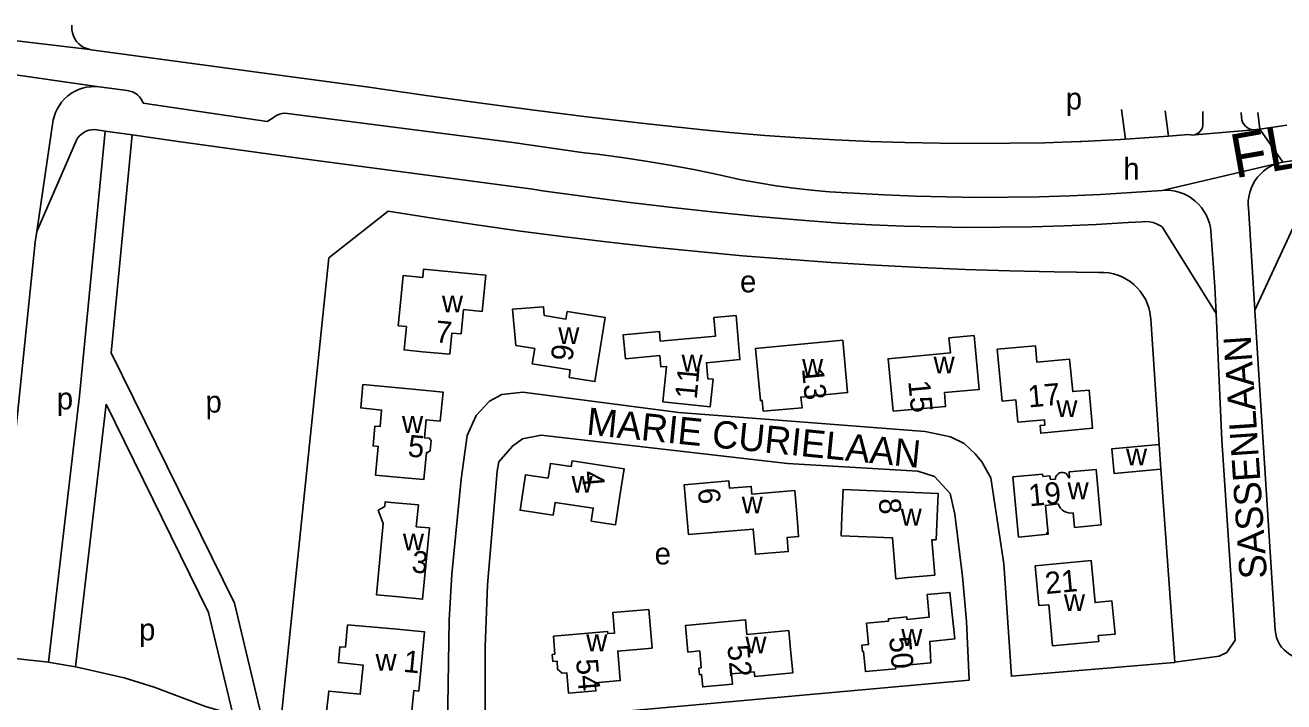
# Model space of a CAD drawing. Extents: x 161093 to 163177, y 379000 to 380904.
# Drawn here: x 162248.8 to 162479, y 380640.8 to 380764.5 of the extents above; entities that cross this region are included whole.
import ezdxf

# ---------------------------------------------------------------- set-up
doc = ezdxf.new("R2010")
doc.units = 0
for name, color, linetype in [('BLT_Basislijn', 7, 'Continuous'), ('BLT_Bebouwing', 7, 'Continuous'), ('BLT_Centroide', 7, 'Continuous'), ('BLT_Huisnummer', 7, 'Continuous'), ('BLT_Straatnaam', 7, 'Continuous'), ('BLT_Straatnaam_hoofdweg', 7, 'Continuous'), ('BLT_Vlakafsluiter', 7, 'Continuous')]:
    doc.layers.add(name, color=color, linetype=linetype)

msp = doc.modelspace()

# ---------------------------------------------------------------- linework, layer by layer
at = {"layer": 'BLT_Basislijn'}
for p, q in [((162262.39, 380753.23), (162267.46, 380752.57)), ((162449.31, 380749.09), (162450.04, 380743.7)), ((162457.32, 380748.88), (162457.95, 380744.25)), ((162464.21, 380748.71), (162464.22, 380746.59)), ((162471.22, 380748.53), (162471.26, 380747.62)), ((162474.25, 380748.54), (162474.64, 380745.52)), ((162261.55, 380745.42), (162263.47, 380745.15)), ((162263.47, 380745.15), (162268.42, 380744.44)), ((162268.42, 380744.44), (162264.57, 380704.6)), ((162268.42, 380744.44), (162276.36, 380743.32)), ((162457.95, 380744.25), (162461.6, 380744.54)), ((162474.64, 380745.52), (162479.59, 380746.21)), ((162258.22, 380743.49), (162250.94, 380726.78)), ((162481.21, 380739.85), (162478.83, 380739.49)), ((162472.53, 380731.15), (162473.7, 380712.42)), ((162481.88, 380730.02), (162473.7, 380712.42)), ((162456.75, 380727.66), (162466.64, 380711.77)), ((162473.7, 380712.42), (162474.2, 380704.45)), ((162466.64, 380711.77), (162467.69, 380688.62)), ((162477.45, 380653.84), (162474.2, 380704.45)), ((162263.64, 380695.17), (162258.02, 380647.15)), ((162253.09, 380647.99), (162254.08, 380647.85)), ((162254.08, 380647.85), (162258.02, 380647.15)), ((162458.95, 380647.95), (162459.11, 380647.98)), ((162258.02, 380647.15), (162258.88, 380647))]:
    msp.add_line(p, q, dxfattribs=at)
for points in [[(162257.39, 380764.52), (162257.36, 380764.24), (162257.39, 380763.67), (162257.49, 380763.1), (162257.67, 380762.55), (162257.93, 380762.04), (162258.25, 380761.56), (162258.64, 380761.14), (162259.08, 380760.77), (162259.57, 380760.47), (162260.1, 380760.23), (162260.65, 380760.08)], [(162260.65, 380760.08), (162260.88, 380760.03), (162290.3, 380756.08), (162311.69, 380753.21)], [(162262.39, 380753.23), (162261.61, 380753.29), (162260.84, 380753.27), (162260.07, 380753.17), (162259.31, 380752.99), (162258.58, 380752.74), (162257.87, 380752.41), (162257.21, 380752.01), (162256.58, 380751.55), (162256.01, 380751.02), (162255.5, 380750.44), (162255.05, 380749.8), (162254.66, 380749.13), (162254.4, 380748.54)], [(162267.46, 380752.57), (162267.97, 380752.48), (162268.46, 380752.32), (162268.93, 380752.08), (162269.35, 380751.78), (162269.73, 380751.42), (162270.04, 380751), (162270.28, 380750.54), (162270.39, 380750.24)], [(162311.69, 380753.21), (162321.76, 380751.72), (162331.83, 380750.3), (162341.92, 380748.97), (162352.02, 380747.72), (162362.12, 380746.55), (162372.24, 380745.45), (162377.73, 380744.89)], [(162294.19, 380747.56), (162293.08, 380746.91), (162270.39, 380750.24)], [(162253.94, 380747.21), (162250.94, 380726.78)], [(162254.4, 380748.54), (162253.94, 380747.21)], [(162296.81, 380748.35), (162296.32, 380748.4), (162295.83, 380748.37), (162295.36, 380748.26), (162294.9, 380748.07), (162294.49, 380747.81), (162294.19, 380747.56)], [(162296.81, 380748.35), (162337.62, 380743.14), (162351.06, 380741.19)], [(162464.22, 380746.59), (162464.21, 380746.19), (162464.13, 380745.8), (162463.97, 380745.44), (162463.74, 380745.11), (162463.45, 380744.84), (162463.11, 380744.63), (162462.74, 380744.49)], [(162471.26, 380747.62), (162471.33, 380747.18), (162471.48, 380746.78), (162471.7, 380746.4), (162471.98, 380746.07), (162472.32, 380745.79), (162472.7, 380745.59), (162473.12, 380745.45), (162473.55, 380745.4)], [(162263.47, 380745.15), (162258.79, 380696.74), (162253.09, 380647.99)], [(162261.55, 380745.42), (162261.02, 380745.41), (162260.5, 380745.32), (162260, 380745.16), (162259.54, 380744.92), (162259.11, 380744.61), (162258.73, 380744.25), (162258.41, 380743.83), (162258.22, 380743.49)], [(162377.73, 380744.89), (162384.11, 380744.37), (162390.5, 380743.92), (162396.9, 380743.55), (162403.3, 380743.27), (162409.7, 380743.06), (162416.1, 380742.93), (162422.51, 380742.89), (162428.91, 380742.92), (162435.32, 380743.03), (162441.72, 380743.23), (162442.1, 380743.24)], [(162450.04, 380743.7), (162456.17, 380744.11), (162457.95, 380744.25)], [(162462.74, 380744.49), (162462.34, 380744.43), (162461.95, 380744.45), (162461.6, 380744.54)], [(162473.55, 380745.4), (162474.01, 380745.43), (162474.64, 380745.52)], [(162341.7, 380734.51), (162298.88, 380740.17), (162276.36, 380743.32)], [(162442.1, 380743.24), (162449.14, 380743.64), (162450.04, 380743.7)], [(162375.44, 380737.2), (162371.09, 380738.1), (162366.71, 380738.91), (162362.33, 380739.66), (162357.93, 380740.32), (162353.52, 380740.9), (162351.06, 380741.19)], [(162478.83, 380739.49), (162478.06, 380739.3), (162477.32, 380739.04), (162476.61, 380738.71), (162475.93, 380738.3), (162475.3, 380737.83), (162474.72, 380737.3), (162474.2, 380736.71), (162473.74, 380736.07), (162473.34, 380735.39), (162473.02, 380734.67), (162472.77, 380733.92), (162472.6, 380733.15), (162472.51, 380732.37), (162472.5, 380731.58), (162472.53, 380731.15)], [(162399.17, 380733.86), (162395.92, 380734.06), (162392.66, 380734.34), (162389.42, 380734.7), (162386.19, 380735.14), (162382.97, 380735.66), (162379.76, 380736.26), (162376.57, 380736.94), (162375.44, 380737.2)], [(162397.78, 380728.29), (162389.99, 380728.91), (162382.21, 380729.6), (162374.43, 380730.37), (162366.67, 380731.22), (162358.91, 380732.15), (162351.16, 380733.17), (162343.43, 380734.25), (162341.7, 380734.51)], [(162456.77, 380734.3), (162451.14, 380733.89), (162445.51, 380733.55), (162439.87, 380733.3), (162434.22, 380733.13), (162428.58, 380733.04), (162422.93, 380733.03), (162417.29, 380733.1), (162411.65, 380733.25), (162406.01, 380733.48), (162400.37, 380733.78), (162399.17, 380733.86)], [(162456.77, 380734.3), (162457.58, 380734.32), (162458.39, 380734.27), (162459.2, 380734.14), (162459.98, 380733.93), (162460.74, 380733.65), (162461.47, 380733.29), (162462.16, 380732.86), (162462.8, 380732.36), (162463.39, 380731.81), (162463.93, 380731.2), (162464.4, 380730.53), (162464.81, 380729.83), (162465.14, 380729.09), (162465.4, 380728.32), (162465.58, 380727.53), (162465.67, 380726.88)], [(162295.46, 380636.01), (162304.37, 380721.94), (162315.24, 380730.53)], [(162315.24, 380730.53), (162323.3, 380729.23), (162331.37, 380728.01), (162339.45, 380726.87), (162347.54, 380725.81), (162355.64, 380724.83), (162363.75, 380723.93), (162371.87, 380723.11), (162379.99, 380722.36), (162388.12, 380721.7), (162396.26, 380721.12), (162404.41, 380720.61), (162412.56, 380720.19), (162420.71, 380719.85), (162428.86, 380719.59), (162437.02, 380719.4), (162445.18, 380719.3), (162445.33, 380719.3)], [(162397.78, 380728.29), (162403.64, 380727.99), (162409.5, 380727.76), (162415.37, 380727.61), (162421.23, 380727.54), (162427.1, 380727.55), (162432.97, 380727.65), (162438.83, 380727.82), (162444.69, 380728.07), (162450.55, 380728.4), (162453.12, 380728.57)], [(162453.12, 380728.57), (162453.79, 380728.6), (162454.46, 380728.54), (162455.11, 380728.4), (162455.75, 380728.19), (162456.36, 380727.9), (162456.75, 380727.66)], [(162250.94, 380726.78), (162250.65, 380724.81), (162242.85, 380649.38)], [(162465.67, 380726.88), (162466.42, 380716.69), (162466.64, 380711.77)], [(162445.33, 380719.3), (162446.18, 380719.29), (162447.02, 380719.2), (162447.86, 380719.03), (162448.67, 380718.79), (162449.46, 380718.47), (162450.21, 380718.07), (162450.93, 380717.61), (162451.6, 380717.08), (162452.21, 380716.5), (162452.77, 380715.85), (162453.26, 380715.16), (162453.69, 380714.43), (162454.05, 380713.65), (162454.33, 380712.85), (162454.53, 380712.02), (162454.66, 380711.18), (162454.69, 380710.76)], [(162454.69, 380710.76), (162456.2, 380687.82)], [(162264.57, 380704.6), (162287.12, 380658.77), (162292.33, 380636.79)], [(162458.95, 380647.95), (162429.2, 380645.44), (162427.8, 380666.02), (162425.43, 380681.74), (162423.8, 380684.63), (162422.56, 380686.13), (162420.55, 380688.02), (162418.06, 380689.25), (162413.44, 380690.18), (162368.4, 380693.69), (162339.82, 380697.42), (162336.03, 380696.95), (162333.77, 380695.77), (162331.31, 380693.12), (162329.69, 380689.49), (162328.59, 380681.48), (162326.85, 380664.09), (162326.39, 380655.74), (162326.05, 380636.17), (162308.65, 380634.63), (162305.5, 380634.73), (162296.83, 380635.69), (162295.46, 380636.01)], [(162263.64, 380695.17), (162282.39, 380657.07), (162286.79, 380638.47)], [(162420.27, 380663.65), (162420.98, 380655.53), (162421.46, 380644.73), (162332.97, 380636.71), (162332.97, 380650.75), (162333.38, 380662.14), (162335.17, 380682.97), (162335.46, 380684.68), (162337.94, 380687.54), (162339.78, 380688.85), (162343.17, 380689.54), (162388.27, 380684.36), (162412.11, 380682.92), (162415.13, 380681.97), (162417.98, 380678.84), (162418.87, 380675.08), (162420.27, 380663.65)], [(162459.11, 380647.98), (162467.2, 380649.13), (162468.58, 380649.78), (162470.11, 380652.01), (162467.69, 380688.62)], [(162456.52, 380683.33), (162459.11, 380647.98)], [(162477.45, 380653.84), (162477.53, 380653.18), (162477.69, 380652.53), (162477.92, 380651.9), (162478.23, 380651.31), (162478.61, 380650.76), (162479.05, 380650.25), (162479.54, 380649.81), (162480.09, 380649.42), (162480.68, 380649.11), (162481.3, 380648.86), (162481.87, 380648.71)], [(162242.85, 380649.38), (162243.05, 380649.1), (162253.09, 380647.99)], [(162286.26, 380638.64), (162281.79, 380639.92), (162272.42, 380643.46), (162266.95, 380645.14), (162258.88, 380647)]]:
    msp.add_lwpolyline(points, dxfattribs=at)
at = {"layer": 'BLT_Bebouwing'}
for p, q in [((162456.52, 380683.33), (162456.2, 380687.82)), ((162439.7, 380681.74), (162439.82, 380681.75))]:
    msp.add_line(p, q, dxfattribs=at)
for points in [[(162321.51, 380704.8), (162326.48, 380704.32), (162326.87, 380708.21), (162328.56, 380708.04), (162329, 380712.49), (162332.39, 380712.15), (162333.05, 380718.78), (162321.67, 380719.87), (162321.53, 380718.38), (162317.95, 380718.72), (162317.47, 380713.74), (162317.06, 380709.54), (162318.56, 380709.4), (162318.14, 380705.12), (162321.51, 380704.8)], [(162338.55, 380705.94), (162337.97, 380712.6), (162343.65, 380713.03), (162343.77, 380711.4)], [(162343.77, 380711.4), (162347.74, 380710.76), (162347.96, 380712.15), (162354.91, 380711.04), (162353.04, 380699.34), (162348.33, 380700.09), (162348.52, 380701.46), (162341.57, 380702.59)], [(162364.98, 380706.71), (162375.06, 380707.64), (162374.75, 380711.03), (162378.83, 380711.41), (162379.55, 380703.36), (162373.42, 380702.77), (162373.7, 380699.86), (162374.66, 380699.75), (162374.1, 380694.69), (162365.43, 380695.65)], [(162364.98, 380706.71), (162364.81, 380708.51), (162358.2, 380707.9), (162358.61, 380703.51), (162364.9, 380704.1)], [(162407.56, 380693.89), (162417.16, 380694.8), (162416.95, 380697.31), (162423.28, 380697.91), (162422.36, 380707.74), (162417.78, 380707.31), (162418.03, 380704.57), (162406.65, 380703.5), (162407.56, 380693.89)], [(162342.02, 380705.38), (162338.55, 380705.94)], [(162341.57, 380702.59), (162342.02, 380705.38)], [(162383.78, 380693.89), (162383.6, 380695.88), (162383.3, 380695.85), (162382.4, 380705.4), (162398.34, 380706.9), (162399.24, 380697.32), (162390.68, 380696.5), (162390.9, 380694.52), (162383.78, 380693.89)], [(162430.39, 380691.92), (162435.23, 380692.35), (162435.31, 380691.38), (162434.46, 380691.31), (162434.57, 380689.89), (162444.03, 380690.78), (162443.4, 380697.78), (162440.4, 380697.51), (162439.84, 380703.41), (162433.87, 380702.87), (162433.6, 380705.87), (162426.6, 380705.24), (162427.49, 380695.77), (162430.03, 380695.99), (162430.39, 380691.92)], [(162365.43, 380695.65), (162366.14, 380702.11), (162365.1, 380702.02), (162364.9, 380704.1)], [(162320.32, 380697.86), (162310.6, 380698.79), (162310.2, 380694.5), (162314.03, 380694.13), (162313.74, 380691.1), (162312.8, 380691.19), (162312.45, 380687.56), (162313.4, 380687.47), (162312.9, 380682.24), (162316.79, 380681.86), (162321.76, 380681.39), (162322.24, 380686.37), (162322.49, 380686.35), (162322.93, 380686.7), (162323.1, 380688.53), (162322.74, 380688.99), (162321.86, 380689.07), (162322.16, 380692.36), (162324.74, 380692.12), (162325.29, 380697.39), (162320.32, 380697.86)], [(162456.2, 380687.82), (162447.59, 380687.03), (162448, 380682.5), (162456.52, 380683.33)], [(162357.61, 380678.45), (162356.8, 380673.13), (162352.36, 380673.81), (162352.73, 380676.18), (162345.73, 380677.24), (162345.37, 380674.88), (162339.34, 380675.79), (162340.33, 380682.3), (162344.46, 380681.69), (162344.88, 380684.36), (162348.69, 380683.77), (162348.87, 380684.85), (162358.36, 380683.39), (162357.61, 380678.45)], [(162430.49, 380670.9), (162429.47, 380681.89), (162434.89, 380682.37), (162434.95, 380681.98), (162436.24, 380682.09), (162436.32, 380681.43), (162437.25, 380681.46)], [(162439.7, 380681.74), (162439.6, 380682.04), (162439.42, 380682.3), (162439.19, 380682.51), (162438.91, 380682.65), (162438.6, 380682.72), (162438.29, 380682.71), (162437.99, 380682.62), (162437.72, 380682.46), (162437.5, 380682.23), (162437.34, 380681.96), (162437.26, 380681.65), (162437.25, 380681.46)], [(162439.82, 380681.75), (162439.74, 380682.82), (162444.68, 380683.27), (162445.62, 380673.13), (162440.72, 380672.67), (162440.49, 380675.33)], [(162389.99, 380674.4), (162389.57, 380679.39), (162381.75, 380678.73), (162381.63, 380680.17), (162377.65, 380679.83), (162377.54, 380681.17), (162369.38, 380680.47), (162369.8, 380675.49), (162370.15, 380671.34), (162381.99, 380672.34), (162382.37, 380667.75), (162388.38, 380668.25), (162388.17, 380670.8), (162390.28, 380670.97), (162389.99, 380674.4)], [(162410.19, 380663.48), (162415.17, 380663.94), (162414.65, 380670.4), (162415.43, 380670.39), (162415.79, 380678.89), (162398.42, 380679.62), (162398.21, 380674.63), (162398.06, 380671.12), (162407.47, 380670.73), (162408.08, 380663.28), (162410.19, 380663.48)], [(162316.54, 380660), (162313.06, 380660.33), (162314.3, 380673.37), (162313.41, 380675.79), (162314.59, 380676.49), (162314.68, 380677.34), (162315.76, 380677.24), (162320.74, 380676.77), (162320.36, 380672.79), (162322.77, 380672.56), (162321.52, 380659.53), (162316.54, 380660)], [(162437.73, 380676.94), (162435.41, 380676.67), (162435.91, 380671.42), (162430.49, 380670.9)], [(162437.73, 380676.94), (162437.9, 380676.54), (162438.15, 380676.17), (162438.45, 380675.86), (162438.81, 380675.6), (162439.2, 380675.42), (162439.62, 380675.31), (162440.06, 380675.28), (162440.49, 380675.33)], [(162435.79, 380671.61), (162435.75, 380671.67), (162435.68, 380671.67), (162435.64, 380671.61), (162435.68, 380671.54), (162435.75, 380671.54), (162435.79, 380671.61), (162435.79, 380671.61)], [(162433.56, 380665.65), (162434.24, 380658.35), (162436.03, 380658.52), (162436.74, 380650.99), (162445.18, 380651.79), (162445.08, 380652.86), (162448.16, 380653.15), (162447.59, 380659.2), (162444.51, 380658.91), (162443.78, 380666.62), (162433.56, 380665.65)], [(162414.18, 380656.22), (162413.78, 380660.37), (162417.96, 380660.77), (162418.83, 380652.25), (162414.25, 380651.79), (162414.47, 380647.9), (162407.99, 380647.26), (162408.04, 380646.8), (162402.49, 380646.28), (162402.14, 380649.95), (162401.99, 380649.94), (162401.87, 380651.13), (162403.07, 380651.24), (162402.7, 380655.13), (162406.74, 380655.51), (162406.69, 380655.96), (162410.06, 380656.28), (162410.1, 380655.83), (162414.18, 380656.22)], [(162345.23, 380649.43), (162345.71, 380649.48), (162345.43, 380652.75), (162355.36, 380653.62), (162355.39, 380653.23), (162356.64, 380653.34), (162356.31, 380657.08), (162362.86, 380657.65), (162363.48, 380650.58), (162357.2, 380650.03), (162357.67, 380644.65), (162353.09, 380644.25), (162353.22, 380642.76), (162348.21, 380642.32), (162347.89, 380646.06), (162347.06, 380645.97), (162346.2, 380646.7), (162346.1, 380648.21), (162345.36, 380648.16), (162345.23, 380649.43)], [(162319.5, 380638.51), (162319.9, 380642.8), (162320.8, 380642.72), (162321.85, 380653.56), (162316.88, 380654.04), (162307.81, 380654.82), (162307.41, 380650.73), (162306.4, 380650.84), (162306.12, 380647.92), (162310.63, 380647.48), (162310.12, 380642.15), (162304.35, 380642.71), (162303.97, 380638.93), (162310.03, 380638.32), (162310.08, 380638.82), (162314.48, 380638.39), (162314.52, 380638.99), (162319.5, 380638.51)], [(162388.75, 380651.01), (162388.49, 380653.79), (162380.82, 380653.07), (162380.57, 380655.77), (162369.6, 380654.74), (162370.05, 380649.86), (162372.2, 380650.06), (162372.49, 380646.99), (162372.05, 380646.91), (162372.17, 380645.72), (162372.54, 380645.77), (162372.76, 380643.49), (162378.17, 380643.98), (162377.98, 380645.89), (162382.15, 380646.27), (162382.25, 380645.37), (162389.21, 380646.03), (162388.75, 380651.01)]]:
    msp.add_lwpolyline(points, dxfattribs=at)
at = {"layer": 'BLT_Vlakafsluiter'}
for p, q in [((162260.65, 380760.08), (162243.54, 380762.07)), ((162240.52, 380756.4), (162262.39, 380753.23)), ((162462.74, 380744.49), (162473.55, 380745.4)), ((162474.64, 380745.52), (162478.83, 380739.49)), ((162456.77, 380734.3), (162478.83, 380739.49))]:
    msp.add_line(p, q, dxfattribs=at)

# ---------------------------------------------------------------- texts
at = {"layer": 'BLT_Centroide'}
for s, p in [('p', (162439.14, 380749.1)), ('h', (162449.66, 380736.25)), ('e', (162379.57, 380715.65)), ('w', (162325.05, 380712)), ('w', (162346.33, 380706.19)), ('w', (162368.88, 380701.17)), ('w', (162390.91, 380700.41)), ('w', (162414.96, 380700.81)), ('p', (162254.63, 380694.24)), ('p', (162281.82, 380693.66)), ('w', (162437.41, 380692.83)), ('w', (162317.75, 380689.94)), ('w', (162450.15, 380684.01)), ('w', (162348.76, 380679)), ('w', (162439.46, 380677.82)), ('w', (162379.87, 380675.22)), ('w', (162408.94, 380672.99)), ('w', (162317.91, 380668.45)), ('e', (162363.95, 380665.88)), ('w', (162438.8, 380657.36)), ('p', (162269.67, 380651.99)), ('w', (162351.44, 380650)), ('w', (162380.55, 380649.62)), ('w', (162409.06, 380650.98)), ('w', (162312.91, 380646.45))]:
    msp.add_text(s, height=4, dxfattribs=at).set_placement(p)
at = {"layer": 'BLT_Huisnummer'}
for s, rotation, p in [('7', 354.5026, (162323.71, 380706.54)), ('9', 82.9821, (162348.9, 380702.93)), ('11', 84.6323, (162371.64, 380696)), ('13', 275.3477, (162390.88, 380701.73)), ('15', 275.3756, (162410.32, 380699.41)), ('17', 5.232, (162432.36, 380694.58)), ('5', 354.5597, (162318.69, 380685.64)), ('4', 274.8188, (162350.63, 380682.87)), ('6', 274.8188, (162371.84, 380679.74)), ('19', 5.4187, (162432.5, 380676.5)), ('8', 274.6923, (162404.9, 380677.88)), ('3', 354.5597, (162319.4, 380664.46)), ('21', 5.3981, (162435.52, 380660.45)), ('50', 275.4433, (162406.81, 380652.53)), ('1', 354.3967, (162317.89, 380646.25)), ('52', 275.361, (162377.24, 380651.04)), ('54', 274.9717, (162349.56, 380648.49))]:
    msp.add_text(s, height=4, rotation=rotation, dxfattribs=at).set_placement(p)
at = {"layer": 'BLT_Straatnaam'}
for s, rotation, p in [('SASSENLAAN', 93.8858, (162475.95, 380663.4)), ('MARIE CURIELAAN', 354.2965, (162351.35, 380689.63))]:
    msp.add_text(s, height=5, rotation=rotation, dxfattribs=at).set_placement(p)
at = {"layer": 'BLT_Straatnaam_hoofdweg'}
msp.add_text('FLORALAAN WEST', height=8, rotation=9.9886, dxfattribs=at).set_placement((162470.07, 380736.5))

doc.saveas('drawing.dxf')
